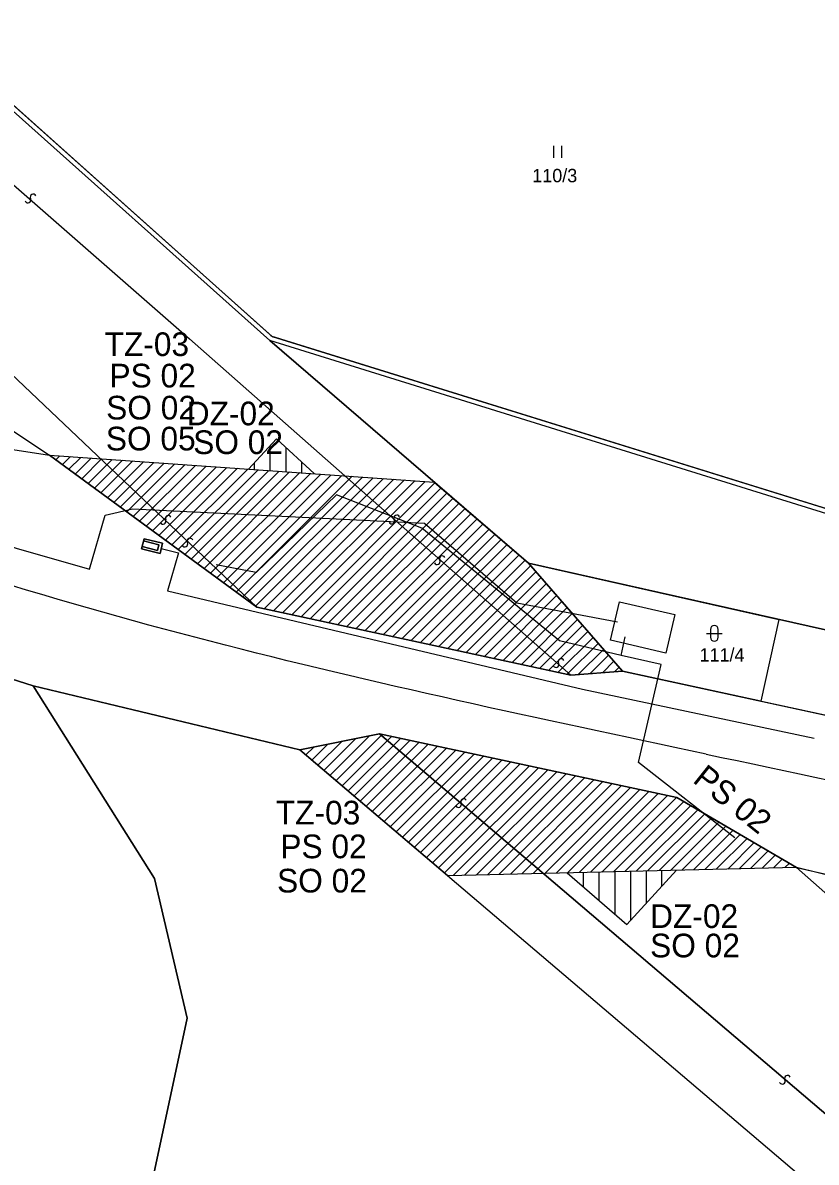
# Model space of a CAD drawing. Extents: x -792659 to -786947, y -1118170 to -1109641.
# Drawn here: x -789641.9 to -789591.6, y -1114317.5 to -1114245.3 of the extents above; entities that cross this region are included whole.
import ezdxf

# ---------------------------------------------------------------- set-up
doc = ezdxf.new("R2010")
doc.units = 0
for name, color, linetype in [('0-Trativody+svodna_potrubi', 7, 'Continuous'), ('1', 7, 'Continuous'), ('Značky kultur', 7, 'Continuous')]:
    doc.layers.add(name, color=color, linetype=linetype)

# ---------------------------------------------------------------- blocks, each defined once
blk = doc.blocks.new('Z30601')
at = {"layer": '1'}
for p, q in [((-0.5, 0), (-0.5, 1.5)), ((0.5, 1.5), (0.5, 0))]:
    blk.add_line(p, q, dxfattribs=at)

msp = doc.modelspace()

# ---------------------------------------------------------------- linework, layer by layer
at = {"layer": '0-Trativody+svodna_potrubi'}
msp.add_lwpolyline([(-789634.353, -1114278.633), (-789633.189, -1114278.925), (-789633.028, -1114278.285), (-789634.192, -1114277.993)], close=True, dxfattribs=at)
msp.add_lwpolyline([(-789634.316, -1114278.488), (-789633.346, -1114278.731), (-789633.259, -1114278.382), (-789634.229, -1114278.139)], dxfattribs=at)
at = {"layer": '1'}
for p, q in [((-789653.29, -1114241.26), (-789626.24, -1114265.44)), ((-789653.09, -1114241.036), (-789626.04, -1114265.216)), ((-789656.61, -1114243.22), (-789631.32, -1114265.33)), ((-789627.07, -1114282.33), (-789662.93, -1114248.27)), ((-789627.07, -1114282.33), (-789662.93, -1114248.27)), ((-789652.15, -1114264.75), (-789640.19, -1114272.7)), ((-789585.63, -1114277.763), (-789626.15, -1114265.153)), ((-789631.32, -1114265.33), (-789607.19, -1114286.63)), ((-789607.19, -1114286.63), (-789631.32, -1114265.33)), ((-789626.24, -1114265.44), (-789609.87, -1114279.55)), ((-789585.72, -1114278.05), (-789626.24, -1114265.44)), ((-789665.23, -1114268.84), (-789640.19, -1114272.7)), ((-789627.58, -1114273.582), (-789625.819, -1114271.659)), ((-789626.21, -1114273.678), (-789626.21, -1114272.086)), ((-789625.819, -1114271.659), (-789623.425, -1114273.872)), ((-789625.21, -1114273.748), (-789625.21, -1114272.222)), ((-789640.19, -1114272.7), (-789627.07, -1114282.33)), ((-789640.19, -1114272.7), (-789615.842, -1114274.403)), ((-789639.782, -1114272.999), (-789639.529, -1114272.746)), ((-789639.374, -1114273.299), (-789638.868, -1114272.792)), ((-789638.967, -1114273.598), (-789638.207, -1114272.839)), ((-789638.559, -1114273.897), (-789637.546, -1114272.885)), ((-789638.151, -1114274.197), (-789636.886, -1114272.931)), ((-789637.743, -1114274.496), (-789636.225, -1114272.977)), ((-789637.335, -1114274.795), (-789635.564, -1114273.024)), ((-789636.928, -1114275.095), (-789634.903, -1114273.07)), ((-789636.52, -1114275.394), (-789634.242, -1114273.116)), ((-789636.112, -1114275.693), (-789633.581, -1114273.162)), ((-789635.704, -1114275.992), (-789632.92, -1114273.208)), ((-789635.297, -1114276.292), (-789632.259, -1114273.255)), ((-789634.889, -1114276.591), (-789631.598, -1114273.301)), ((-789634.481, -1114276.89), (-789630.938, -1114273.347)), ((-789634.073, -1114277.19), (-789630.277, -1114273.393)), ((-789633.665, -1114277.489), (-789629.616, -1114273.439)), ((-789633.258, -1114277.788), (-789628.955, -1114273.486)), ((-789632.85, -1114278.088), (-789628.294, -1114273.532)), ((-789632.442, -1114278.387), (-789627.633, -1114273.578)), ((-789632.034, -1114278.686), (-789626.972, -1114273.624)), ((-789631.626, -1114278.986), (-789626.311, -1114273.671)), ((-789631.219, -1114279.285), (-789625.65, -1114273.717)), ((-789630.811, -1114279.584), (-789624.99, -1114273.763)), ((-789630.403, -1114279.884), (-789624.329, -1114273.809)), ((-789627.21, -1114273.608), (-789627.21, -1114273.178)), ((-789624.21, -1114273.818), (-789624.21, -1114273.147)), ((-789629.995, -1114280.183), (-789623.668, -1114273.855)), ((-789629.587, -1114280.482), (-789623.007, -1114273.902)), ((-789629.18, -1114280.782), (-789622.346, -1114273.948)), ((-789628.772, -1114281.081), (-789621.685, -1114273.994)), ((-789628.364, -1114281.38), (-789621.024, -1114274.04)), ((-789627.956, -1114281.679), (-789620.363, -1114274.087)), ((-789627.548, -1114281.979), (-789619.702, -1114274.133)), ((-789627.141, -1114282.278), (-789619.042, -1114274.179)), ((-789626.589, -1114282.434), (-789618.381, -1114274.225)), ((-789626.008, -1114282.56), (-789617.72, -1114274.271)), ((-789625.427, -1114282.685), (-789617.059, -1114274.318)), ((-789624.845, -1114282.811), (-789616.398, -1114274.364)), ((-789624.264, -1114282.937), (-789615.782, -1114274.455)), ((-789637.05, -1114275), (-789637.05, -1114275)), ((-789622.017, -1114275.21), (-789627.103, -1114280.14)), ((-789622.017, -1114275.21), (-789627.103, -1114280.14)), ((-789623.683, -1114283.063), (-789615.402, -1114274.782)), ((-789623.101, -1114283.188), (-789615.022, -1114275.109)), ((-789616.62, -1114277.336), (-789622.017, -1114275.21)), ((-789622.52, -1114283.314), (-789614.642, -1114275.437)), ((-789621.939, -1114283.44), (-789614.263, -1114275.764)), ((-789621.357, -1114283.566), (-789613.883, -1114276.091)), ((-789620.776, -1114283.691), (-789613.503, -1114276.419)), ((-789620.194, -1114283.817), (-789613.123, -1114276.746)), ((-789619.613, -1114283.943), (-789612.743, -1114277.073)), ((-789619.032, -1114284.069), (-789612.364, -1114277.401)), ((-789607.895, -1114284.455), (-789616.62, -1114277.336)), ((-789634.353, -1114278.633), (-789634.192, -1114277.993)), ((-789634.229, -1114278.139), (-789633.259, -1114278.382)), ((-789634.192, -1114277.993), (-789633.028, -1114278.285)), ((-789618.45, -1114284.194), (-789611.984, -1114277.728)), ((-789617.869, -1114284.32), (-789611.604, -1114278.055)), ((-789633.189, -1114278.925), (-789634.353, -1114278.633)), ((-789633.346, -1114278.731), (-789634.316, -1114278.488)), ((-789633.259, -1114278.382), (-789633.346, -1114278.731)), ((-789633.028, -1114278.285), (-789633.189, -1114278.925)), ((-789617.288, -1114284.446), (-789611.224, -1114278.383)), ((-789616.706, -1114284.572), (-789610.845, -1114278.71)), ((-789667.235, -1114279.043), (-789641.23, -1114287.32)), ((-789616.125, -1114284.697), (-789610.465, -1114279.037)), ((-789615.544, -1114284.823), (-789610.085, -1114279.365)), ((-789609.87, -1114279.55), (-789609.87, -1114279.55)), ((-789609.87, -1114279.55), (-789603.91, -1114286.39)), ((-789586.59, -1114284.77), (-789609.87, -1114279.55)), ((-789609.87, -1114279.55), (-789586.59, -1114284.77)), ((-789627.103, -1114280.14), (-789629.63, -1114279.651)), ((-789627.103, -1114280.14), (-789629.63, -1114279.651)), ((-789614.962, -1114284.949), (-789609.727, -1114279.714)), ((-789614.381, -1114285.075), (-789609.398, -1114280.092)), ((-789613.8, -1114285.2), (-789609.069, -1114280.47)), ((-789613.218, -1114285.326), (-789608.739, -1114280.847)), ((-789612.637, -1114285.452), (-789608.41, -1114281.225)), ((-789612.055, -1114285.578), (-789608.081, -1114281.603)), ((-789627.07, -1114282.33), (-789607.19, -1114286.63)), ((-789611.474, -1114285.703), (-789607.752, -1114281.981)), ((-789610.893, -1114285.829), (-789607.422, -1114282.359)), ((-789604.67, -1114284.433), (-789604.109, -1114281.997)), ((-789604.67, -1114284.433), (-789604.109, -1114281.997)), ((-789604.109, -1114281.997), (-789600.601, -1114282.805)), ((-789604.109, -1114281.997), (-789600.601, -1114282.805)), ((-789610.311, -1114285.955), (-789607.093, -1114282.737)), ((-789609.73, -1114286.081), (-789606.764, -1114283.115)), ((-789600.601, -1114282.805), (-789601.162, -1114285.241)), ((-789600.601, -1114282.805), (-789601.162, -1114285.241)), ((-789594.01, -1114283.11), (-789595.15, -1114288.29)), ((-789609.149, -1114286.206), (-789606.435, -1114283.492)), ((-789608.567, -1114286.332), (-789606.105, -1114283.87)), ((-789607.986, -1114286.458), (-789605.776, -1114284.248)), ((-789604.002, -1114285.394), (-789607.895, -1114284.455)), ((-789604.002, -1114285.394), (-789607.895, -1114284.455)), ((-789604.002, -1114285.394), (-789607.895, -1114284.455)), ((-789607.405, -1114286.584), (-789605.447, -1114284.626)), ((-789601.162, -1114285.241), (-789604.67, -1114284.433)), ((-789601.162, -1114285.241), (-789604.67, -1114284.433)), ((-789606.709, -1114286.595), (-789605.118, -1114285.004)), ((-789605.946, -1114286.539), (-789604.789, -1114285.382)), ((-789605.183, -1114286.483), (-789604.459, -1114285.76)), ((-789607.19, -1114286.63), (-789603.91, -1114286.39)), ((-789604.42, -1114286.427), (-789604.13, -1114286.137)), ((-789603.91, -1114286.39), (-789562.235, -1114295.417)), ((-789603.91, -1114286.39), (-789562.26, -1114295.41)), ((-789641.23, -1114287.32), (-789624.34, -1114291.37)), ((-789641.23, -1114287.32), (-789633.53, -1114299.52)), ((-789633.53, -1114299.52), (-789641.23, -1114287.32)), ((-789624.34, -1114291.37), (-789619.3, -1114290.36)), ((-789624.34, -1114291.37), (-789619.3, -1114290.36)), ((-789622.048, -1114293.321), (-789619.125, -1114290.397)), ((-789562.235, -1114339.028), (-789619.3, -1114290.36)), ((-789619.3, -1114290.36), (-789600.46, -1114294.39)), ((-789619.3, -1114290.36), (-789562.235, -1114339.028)), ((-789619.3, -1114290.36), (-789600.46, -1114294.39)), ((-789623.576, -1114292.02), (-789622.571, -1114291.016)), ((-789623.194, -1114292.345), (-789621.687, -1114290.838)), ((-789622.812, -1114292.671), (-789620.803, -1114290.661)), ((-789622.43, -1114292.996), (-789619.918, -1114290.484)), ((-789621.666, -1114293.646), (-789618.542, -1114290.522)), ((-789621.284, -1114293.971), (-789617.96, -1114290.647)), ((-789620.902, -1114294.296), (-789617.377, -1114290.771)), ((-789620.52, -1114294.621), (-789616.795, -1114290.896)), ((-789620.138, -1114294.947), (-789616.212, -1114291.02)), ((-789624.34, -1114291.37), (-789575.6, -1114332.86)), ((-789624.34, -1114291.37), (-789575.6, -1114332.86)), ((-789623.958, -1114291.695), (-789623.456, -1114291.193)), ((-789619.756, -1114295.272), (-789615.63, -1114291.145)), ((-789619.375, -1114295.597), (-789615.047, -1114291.27)), ((-789618.993, -1114295.922), (-789614.465, -1114291.394)), ((-789618.611, -1114296.247), (-789613.882, -1114291.519)), ((-789618.229, -1114296.572), (-789613.3, -1114291.643)), ((-789617.847, -1114296.897), (-789612.717, -1114291.768)), ((-789617.465, -1114297.223), (-789612.135, -1114291.893)), ((-789617.083, -1114297.548), (-789611.552, -1114292.017)), ((-789616.701, -1114297.873), (-789610.97, -1114292.142)), ((-789616.319, -1114298.198), (-789610.387, -1114292.266)), ((-789615.937, -1114298.523), (-789609.805, -1114292.391)), ((-789615.555, -1114298.848), (-789609.222, -1114292.516)), ((-789615.173, -1114299.173), (-789608.64, -1114292.64)), ((-789614.629, -1114299.337), (-789608.057, -1114292.765)), ((-789613.905, -1114299.32), (-789607.475, -1114292.89)), ((-789613.181, -1114299.303), (-789606.892, -1114293.014)), ((-789612.456, -1114299.285), (-789606.31, -1114293.139)), ((-789611.732, -1114299.268), (-789605.727, -1114293.263)), ((-789611.008, -1114299.251), (-789605.145, -1114293.388)), ((-789610.283, -1114299.234), (-789604.562, -1114293.513)), ((-789609.559, -1114299.216), (-789603.98, -1114293.637)), ((-789608.835, -1114299.199), (-789603.397, -1114293.762)), ((-789608.11, -1114299.182), (-789602.815, -1114293.886)), ((-789607.386, -1114299.165), (-789602.232, -1114294.011)), ((-789602.15, -1114294.03), (-789602.15, -1114294.03)), ((-789606.662, -1114299.148), (-789601.65, -1114294.136)), ((-789605.937, -1114299.13), (-789601.067, -1114294.26)), ((-789605.213, -1114299.113), (-789600.485, -1114294.385)), ((-789604.489, -1114299.096), (-789600.033, -1114294.64)), ((-789600.46, -1114294.39), (-789592.9, -1114298.82)), ((-789600.46, -1114294.39), (-789592.9, -1114298.82)), ((-789603.764, -1114299.079), (-789599.587, -1114294.901)), ((-789603.04, -1114299.061), (-789599.141, -1114295.163)), ((-789602.316, -1114299.044), (-789598.695, -1114295.424)), ((-789601.591, -1114299.027), (-789598.25, -1114295.685)), ((-789600.867, -1114299.01), (-789597.804, -1114295.946)), ((-789600.143, -1114298.992), (-789597.358, -1114296.208)), ((-789599.418, -1114298.975), (-789596.912, -1114296.469)), ((-789598.694, -1114298.958), (-789596.466, -1114296.73)), ((-789597.97, -1114298.941), (-789596.02, -1114296.992)), ((-789597.245, -1114298.923), (-789595.575, -1114297.253)), ((-789596.521, -1114298.906), (-789595.129, -1114297.514)), ((-789595.796, -1114298.889), (-789594.683, -1114297.775)), ((-789595.072, -1114298.872), (-789594.237, -1114298.037)), ((-789594.348, -1114298.854), (-789593.791, -1114298.298)), ((-789592.9, -1114298.82), (-789614.971, -1114299.345)), ((-789603.642, -1114302.433), (-789600.497, -1114299.001)), ((-789603.379, -1114302.146), (-789603.379, -1114299.069)), ((-789602.379, -1114301.055), (-789602.379, -1114299.046)), ((-789601.42, -1114300.008), (-789601.42, -1114299.023)), ((-789593.623, -1114298.837), (-789593.345, -1114298.559)), ((-789592.9, -1114298.82), (-789562.235, -1114325.922)), ((-789592.9, -1114298.82), (-789590.47, -1114299.37)), ((-789633.53, -1114299.52), (-789631.47, -1114308.38)), ((-789631.47, -1114308.38), (-789633.53, -1114299.52)), ((-789607.406, -1114299.165), (-789603.642, -1114302.433)), ((-789606.379, -1114300.057), (-789606.379, -1114299.141)), ((-789605.379, -1114300.925), (-789605.379, -1114299.117)), ((-789604.379, -1114301.793), (-789604.379, -1114299.093)), ((-789631.47, -1114308.38), (-789635.04, -1114325.1)), ((-789635.04, -1114325.1), (-789631.47, -1114308.38))]:
    msp.add_line(p, q, dxfattribs=at)
for points in [[(-789674.01, -1114222.232), (-789653.09, -1114241.037), (-789626.089, -1114265.173), (-789585.645, -1114277.759), (-789547.205, -1114285.569), (-789509.71, -1114297.224), (-789475.119, -1114308.284), (-789456.079, -1114314.364), (-789451.572, -1114315.806)], [(-789534.18, -1114315.38), (-789561.38, -1114306.6), (-789562.235, -1114306.385), (-789592.9, -1114298.82), (-789600.46, -1114294.39), (-789619.3, -1114290.36), (-789624.34, -1114291.37), (-789641.23, -1114287.32), (-789672.68, -1114277.31), (-789724.61, -1114250.58), (-789729.37, -1114244.66), (-789729.37, -1114234.086), (-789721.98, -1114237.82), (-789717.72, -1114240.35), (-789691.28, -1114256.01), (-789665.23, -1114268.84), (-789640.19, -1114272.7), (-789627.07, -1114282.33), (-789607.19, -1114286.63), (-789603.91, -1114286.39), (-789562.235, -1114295.417), (-789557.19, -1114296.51), (-789534.19, -1114304.37)], [(-789729.37, -1114235.184), (-789723.862, -1114237.997), (-789721.431, -1114240.246), (-789715.579, -1114243.503), (-789712.528, -1114244.57), (-789693.799, -1114256.222), (-789674.69, -1114266.079), (-789667.235, -1114269.285), (-789659.833, -1114272.468), (-789642.291, -1114278.583), (-789637.658, -1114279.919), (-789636.672, -1114276.495), (-789634.932, -1114276.106), (-789616.443, -1114277.002), (-789610.603, -1114282.06), (-789604.228, -1114283.252)], [(-789729.37, -1114235.184), (-789723.862, -1114237.997), (-789721.431, -1114240.246), (-789715.579, -1114243.503), (-789712.528, -1114244.57), (-789693.799, -1114256.222), (-789674.69, -1114266.079), (-789667.235, -1114269.285), (-789659.833, -1114272.468), (-789642.291, -1114278.583), (-789637.658, -1114279.919), (-789636.672, -1114276.495), (-789634.932, -1114276.106), (-789616.443, -1114277.002), (-789610.603, -1114282.06), (-789604.228, -1114283.252)], [(-789652.15, -1114264.75), (-789640.19, -1114272.7), (-789627.07, -1114282.33), (-789607.19, -1114286.63), (-789603.91, -1114286.39), (-789609.87, -1114279.55), (-789626.24, -1114265.44)], [(-789667.235, -1114269.285), (-789659.833, -1114272.468), (-789642.291, -1114278.583), (-789637.658, -1114279.919), (-789636.672, -1114276.495), (-789634.932, -1114276.106), (-789616.443, -1114277.002), (-789610.603, -1114282.06), (-789604.228, -1114283.252)], [(-789667.235, -1114269.285), (-789659.833, -1114272.468), (-789642.291, -1114278.583), (-789637.658, -1114279.919), (-789636.672, -1114276.495), (-789634.932, -1114276.106), (-789616.443, -1114277.002), (-789610.603, -1114282.06), (-789604.228, -1114283.252)], [(-789667.235, -1114269.285), (-789659.833, -1114272.468), (-789642.291, -1114278.583), (-789637.658, -1114279.919), (-789636.672, -1114276.495), (-789634.932, -1114276.106), (-789616.443, -1114277.002), (-789610.603, -1114282.06), (-789604.228, -1114283.252)], [(-789633.108, -1114278.605), (-789632.026, -1114278.891), (-789632.718, -1114281.294), (-789606.445, -1114287.517), (-789591.773, -1114290.639)], [(-789633.108, -1114278.605), (-789632.026, -1114278.891), (-789632.718, -1114281.294), (-789606.445, -1114287.517), (-789591.773, -1114290.639)], [(-789598.616, -1114291.638), (-789599.6, -1114291.43), (-789600.585, -1114291.221), (-789601.569, -1114291.012), (-789602.554, -1114290.803), (-789603.538, -1114290.594), (-789604.522, -1114290.384), (-789605.506, -1114290.174), (-789606.49, -1114289.963), (-789607.474, -1114289.751), (-789608.457, -1114289.538), (-789609.441, -1114289.325), (-789610.424, -1114289.111), (-789611.407, -1114288.896), (-789612.39, -1114288.679), (-789613.372, -1114288.461), (-789614.354, -1114288.243), (-789615.336, -1114288.022), (-789616.318, -1114287.801), (-789617.299, -1114287.577), (-789618.28, -1114287.352), (-789619.26, -1114287.126), (-789620.24, -1114286.897), (-789621.22, -1114286.667), (-789622.199, -1114286.435), (-789623.178, -1114286.2), (-789624.156, -1114285.964), (-789625.133, -1114285.725), (-789626.11, -1114285.484), (-789627.087, -1114285.241), (-789628.063, -1114284.995), (-789629.038, -1114284.746), (-789630.012, -1114284.495), (-789630.986, -1114284.241), (-789631.959, -1114283.985), (-789632.931, -1114283.725), (-789633.903, -1114283.463), (-789634.873, -1114283.197), (-789635.843, -1114282.928), (-789636.812, -1114282.657), (-789637.78, -1114282.381), (-789638.747, -1114282.103), (-789639.713, -1114281.821), (-789640.678, -1114281.535), (-789641.642, -1114281.246), (-789642.604, -1114280.953)], [(-789598.616, -1114291.638), (-789599.6, -1114291.43), (-789600.585, -1114291.221), (-789601.569, -1114291.012), (-789602.554, -1114290.803), (-789603.538, -1114290.594), (-789604.522, -1114290.384), (-789605.506, -1114290.174), (-789606.49, -1114289.963), (-789607.474, -1114289.751), (-789608.457, -1114289.538), (-789609.441, -1114289.325), (-789610.424, -1114289.111), (-789611.407, -1114288.896), (-789612.39, -1114288.679), (-789613.372, -1114288.461), (-789614.354, -1114288.243), (-789615.336, -1114288.022), (-789616.318, -1114287.801), (-789617.299, -1114287.577), (-789618.28, -1114287.352), (-789619.26, -1114287.126), (-789620.24, -1114286.897), (-789621.22, -1114286.667), (-789622.199, -1114286.435), (-789623.178, -1114286.2), (-789624.156, -1114285.964), (-789625.133, -1114285.725), (-789626.11, -1114285.484), (-789627.087, -1114285.241), (-789628.063, -1114284.995), (-789629.038, -1114284.746), (-789630.012, -1114284.495), (-789630.986, -1114284.241), (-789631.959, -1114283.985), (-789632.931, -1114283.725), (-789633.903, -1114283.463), (-789634.873, -1114283.197), (-789635.843, -1114282.928), (-789636.812, -1114282.657), (-789637.78, -1114282.381), (-789638.747, -1114282.103), (-789639.713, -1114281.821), (-789640.678, -1114281.535), (-789641.642, -1114281.246), (-789642.604, -1114280.953)], [(-789598.616, -1114291.638), (-789599.6, -1114291.43), (-789600.585, -1114291.221), (-789601.569, -1114291.012), (-789602.554, -1114290.803), (-789603.538, -1114290.594), (-789604.522, -1114290.384), (-789605.506, -1114290.174), (-789606.49, -1114289.963), (-789607.474, -1114289.751), (-789608.457, -1114289.538), (-789609.441, -1114289.325), (-789610.424, -1114289.111), (-789611.407, -1114288.896), (-789612.39, -1114288.679), (-789613.372, -1114288.461), (-789614.354, -1114288.243), (-789615.336, -1114288.022), (-789616.318, -1114287.801), (-789617.299, -1114287.577), (-789618.28, -1114287.352), (-789619.26, -1114287.126), (-789620.24, -1114286.897), (-789621.22, -1114286.667), (-789622.199, -1114286.435), (-789623.178, -1114286.2), (-789624.156, -1114285.964), (-789625.133, -1114285.725), (-789626.11, -1114285.484), (-789627.087, -1114285.241), (-789628.063, -1114284.995), (-789629.038, -1114284.746), (-789630.012, -1114284.495), (-789630.986, -1114284.241), (-789631.959, -1114283.985), (-789632.931, -1114283.725), (-789633.903, -1114283.463), (-789634.873, -1114283.197), (-789635.843, -1114282.928), (-789636.812, -1114282.657), (-789637.78, -1114282.381), (-789638.747, -1114282.103), (-789639.713, -1114281.821), (-789640.678, -1114281.535), (-789641.642, -1114281.246), (-789642.604, -1114280.953)], [(-789598.616, -1114291.638), (-789599.6, -1114291.43), (-789600.585, -1114291.221), (-789601.569, -1114291.012), (-789602.554, -1114290.803), (-789603.538, -1114290.594), (-789604.522, -1114290.384), (-789605.506, -1114290.174), (-789606.49, -1114289.963), (-789607.474, -1114289.751), (-789608.457, -1114289.538), (-789609.441, -1114289.325), (-789610.424, -1114289.111), (-789611.407, -1114288.896), (-789612.39, -1114288.679), (-789613.372, -1114288.461), (-789614.354, -1114288.243), (-789615.336, -1114288.022), (-789616.318, -1114287.801), (-789617.299, -1114287.577), (-789618.28, -1114287.352), (-789619.26, -1114287.126), (-789620.24, -1114286.897), (-789621.22, -1114286.667), (-789622.199, -1114286.435), (-789623.178, -1114286.2), (-789624.156, -1114285.964), (-789625.133, -1114285.725), (-789626.11, -1114285.484), (-789627.087, -1114285.241), (-789628.063, -1114284.995), (-789629.038, -1114284.746), (-789630.012, -1114284.495), (-789630.986, -1114284.241), (-789631.959, -1114283.985), (-789632.931, -1114283.725), (-789633.903, -1114283.463), (-789634.873, -1114283.197), (-789635.843, -1114282.928), (-789636.812, -1114282.657), (-789637.78, -1114282.381), (-789638.747, -1114282.103), (-789639.713, -1114281.821), (-789640.678, -1114281.535), (-789641.642, -1114281.246), (-789642.604, -1114280.953)], [(-789596.798, -1114296.952), (-789602.888, -1114292.179), (-789601.463, -1114285.958), (-789604.002, -1114285.394), (-789603.736, -1114284.207)], [(-789596.798, -1114296.952), (-789602.888, -1114292.179), (-789601.463, -1114285.958), (-789604.002, -1114285.394), (-789603.736, -1114284.207)], [(-789596.798, -1114296.952), (-789602.888, -1114292.179), (-789601.463, -1114285.958), (-789604.002, -1114285.394), (-789603.736, -1114284.207)], [(-789596.798, -1114296.952), (-789602.888, -1114292.179), (-789601.463, -1114285.958), (-789604.002, -1114285.394), (-789603.736, -1114284.207)], [(-789598.616, -1114291.638), (-789597.631, -1114291.847), (-789596.647, -1114292.056), (-789595.663, -1114292.264), (-789594.678, -1114292.474), (-789593.694, -1114292.683), (-789592.71, -1114292.893), (-789591.726, -1114293.103), (-789590.742, -1114293.314)], [(-789598.616, -1114291.638), (-789597.631, -1114291.847), (-789596.647, -1114292.056), (-789595.663, -1114292.264), (-789594.678, -1114292.474), (-789593.694, -1114292.683), (-789592.71, -1114292.893), (-789591.726, -1114293.103), (-789590.742, -1114293.314)], [(-789598.616, -1114291.638), (-789597.631, -1114291.847), (-789596.647, -1114292.056), (-789595.663, -1114292.264), (-789594.678, -1114292.474), (-789593.694, -1114292.683), (-789592.71, -1114292.893), (-789591.726, -1114293.103), (-789590.742, -1114293.314)], [(-789598.616, -1114291.638), (-789597.631, -1114291.847), (-789596.647, -1114292.056), (-789595.663, -1114292.264), (-789594.678, -1114292.474), (-789593.694, -1114292.683), (-789592.71, -1114292.893), (-789591.726, -1114293.103), (-789590.742, -1114293.314)]]:
    msp.add_lwpolyline(points, dxfattribs=at)
for points in [[(-789640.19, -1114272.7), (-789615.842, -1114274.403), (-789609.87, -1114279.55), (-789603.91, -1114286.39), (-789607.19, -1114286.63), (-789627.07, -1114282.33)], [(-789609.87, -1114279.55), (-789594.01, -1114283.11), (-789595.15, -1114288.29), (-789603.91, -1114286.39)], [(-789624.34, -1114291.37), (-789619.3, -1114290.36), (-789600.46, -1114294.39), (-789592.9, -1114298.82), (-789614.971, -1114299.345)]]:
    msp.add_lwpolyline(points, close=True, dxfattribs=at)
for centre, radius, start, end in [((-789641.552, -1114256.524), 0.188, 207.58203, 27.58203), ((-789641.219, -1114256.35), 0.188, 27.58203, 207.58202), ((-789632.667, -1114276.712), 0.187, 27.58203, 207.58202), ((-789618.189, -1114276.69), 0.188, 27.58203, 207.58202), ((-789633, -1114276.885), 0.188, 207.58203, 27.58203), ((-789618.522, -1114276.864), 0.188, 207.58203, 27.58203), ((-789631.289, -1114278.15), 0.188, 27.58203, 207.58202), ((-789631.622, -1114278.324), 0.188, 207.58203, 27.58203), ((-789615.65, -1114279.445), 0.187, 207.58203, 27.58203), ((-789615.317, -1114279.272), 0.187, 27.58203, 207.58202), ((-789608.122, -1114285.964), 0.188, 207.58203, 27.58203), ((-789607.789, -1114285.79), 0.188, 27.58203, 207.58202), ((-789614.297, -1114294.83), 0.188, 207.58203, 27.58203), ((-789613.965, -1114294.656), 0.187, 27.58202, 207.58202), ((-789593.459, -1114312.19), 0.188, 27.58203, 207.58202), ((-789593.792, -1114312.364), 0.188, 207.58203, 27.58203)]:
    msp.add_arc(centre, radius, start, end, dxfattribs=at)
at = {"layer": 'Značky kultur'}
for p, q in [((-789598.345, -1114283.74), (-789598.345, -1114284.24)), ((-789598.345, -1114283.74), (-789598.345, -1114284.24)), ((-789597.845, -1114284.24), (-789597.845, -1114283.74)), ((-789597.845, -1114284.24), (-789597.845, -1114283.74)), ((-789598.595, -1114283.99), (-789597.595, -1114283.99)), ((-789598.595, -1114283.99), (-789597.595, -1114283.99))]:
    msp.add_line(p, q, dxfattribs=at)
for centre, start, end in [((-789598.095, -1114283.74), 0, 180), ((-789598.095, -1114283.74), 0, 180), ((-789598.095, -1114284.24), 180, 359.98789), ((-789598.095, -1114284.24), 180, 359.98789)]:
    msp.add_arc(centre, 0.25, start, end, dxfattribs=at)

# ---------------------------------------------------------------- block references
at = {"layer": '1', "xscale": 0.5, "yscale": 0.5}
msp.add_blockref('Z30601', (-789608.015, -1114253.86), dxfattribs=at)

# ---------------------------------------------------------------- texts
at = {"layer": '1'}
for s, height, p in [('110/3', 0.85, (-789609.62, -1114255.41)), ('TZ-03', 1.5, (-789636.7, -1114266.42)), ('PS 02', 1.5, (-789636.39, -1114268.41)), ('SO 02', 1.5, (-789636.6, -1114270.44)), ('DZ-02', 1.5, (-789631.5, -1114270.81)), ('SO 05', 1.5, (-789636.62, -1114272.4)), ('SO 02', 1.5, (-789631.09, -1114272.63)), ('111/4', 0.85, (-789599.03, -1114285.78)), ('TZ-03', 1.5, (-789625.86, -1114296.1)), ('PS 02', 1.5, (-789625.57, -1114298.24)), ('SO 02', 1.5, (-789625.78, -1114300.41)), ('DZ-02', 1.5, (-789602.16, -1114302.66)), ('SO 02', 1.5, (-789602.16, -1114304.52))]:
    msp.add_text(s, height=height, dxfattribs=at).set_placement(p)
msp.add_text('PS 02', height=1.5, rotation=321.47204, dxfattribs=at).set_placement((-789599.53, -1114293.38))

doc.saveas('drawing.dxf')
